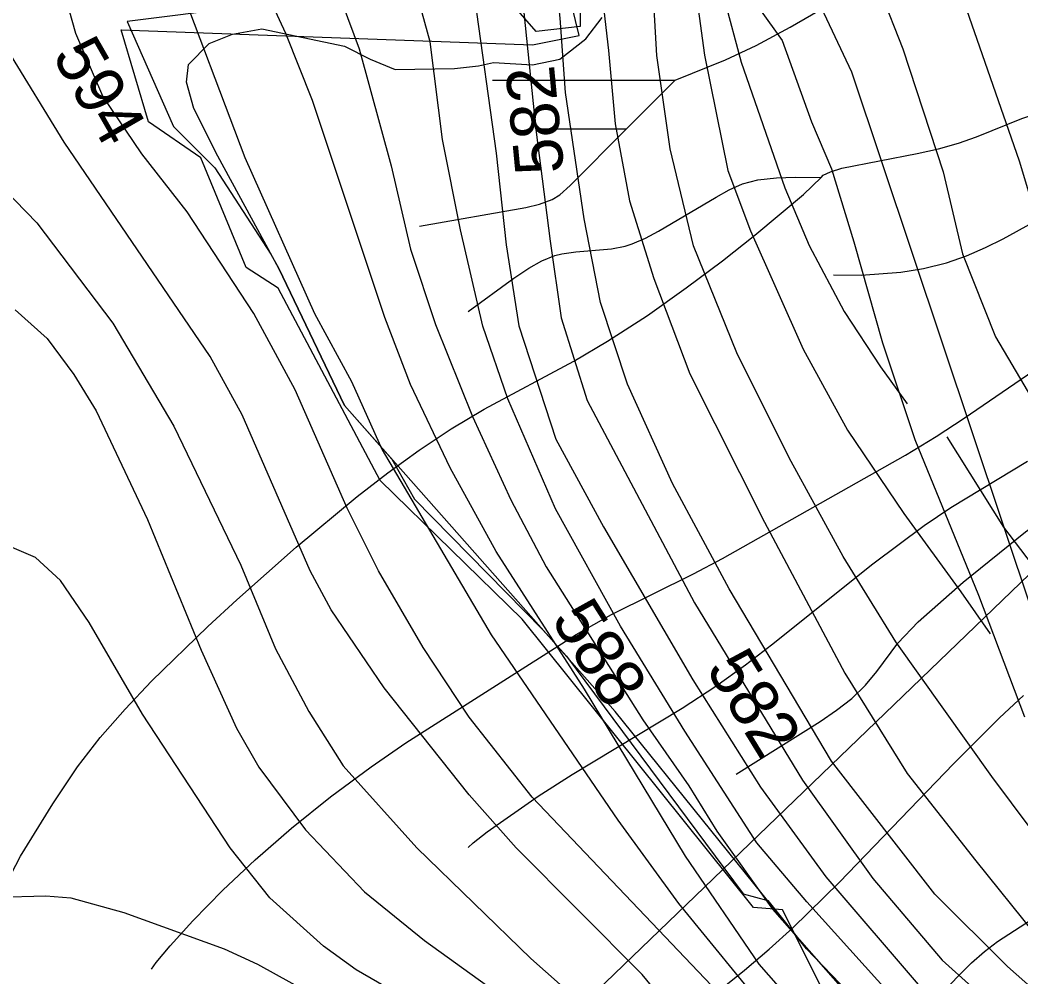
# Model space of a CAD drawing. Extents: x -709584 to -702006, y -1161789 to -1157496.
# Drawn here: x -708051.5 to -707846, y -1159256.1 to -1159059.7 of the extents above; entities that cross this region are included whole.
import ezdxf

# ---------------------------------------------------------------- set-up
doc = ezdxf.new("R2010")
doc.units = 0
for name, color, linetype in [('102_obvod PÚ', 7, 'Continuous'), ('120_vrstevnice hlavní', 7, 'Continuous'), ('121_vrstevnice hlavní_popis', 7, 'Continuous'), ('122_vrstevnice základní', 7, 'Continuous'), ('408_BPEJ_linie', 7, 'Continuous'), ('411_akumulovaný odtok', 7, 'Continuous'), ('419_LPIS PB', 7, 'Continuous')]:
    doc.layers.add(name, color=color, linetype=linetype)

msp = doc.modelspace()

# ---------------------------------------------------------------- linework, layer by layer
at = {"layer": '102_obvod PÚ'}
msp.add_lwpolyline([(-707886.77, -1159258.66), (-707894.98, -1159242.32), (-707900.9, -1159241.82), (-707948.43, -1159182.66), (-707977.59, -1159154.21), (-707998.52, -1159114.69), (-708005.08, -1159110.48), (-708014.36, -1159087.93), (-708025.14, -1159080.58), (-708030.74, -1159061.67), (-707946.25, -1159064.74), (-707936.69, -1159062.88), (-707939.76, -1159050.18), (-707956.24, -1159018.71), (-707933.55, -1159011.72), (-707932.26, -1159006.15), (-707944.32, -1158991.81), (-707921.75, -1158971.03), (-707999.13, -1158885.41)], dxfattribs=at)
at = {"layer": '120_vrstevnice hlavní'}
for points in [[(-707848.73, -1159253.97), (-707863.68, -1159239.08), (-707884.91, -1159211.8), (-707905.93, -1159176.45), (-707917.51, -1159154.82), (-707926.81, -1159134.44), (-707932.34, -1159117.65), (-707935.66, -1159100.46), (-707939.49, -1159074.58), (-707940.61, -1159059.3), (-707941.75, -1159048.16), (-707943.46, -1159040.73), (-707948.46, -1159025.87), (-707951.89, -1159018.44), (-707957.89, -1159007.3), (-707967.47, -1158995.44), (-707982.61, -1158980.3), (-708017.04, -1158950.58), (-708039.04, -1158933.58), (-708068.19, -1158914.44)], [(-707842.05, -1159330.03), (-707850.89, -1159310.21), (-707856.39, -1159300.65), (-707860.67, -1159294.5), (-707886.32, -1159268.74), (-707899.75, -1159253.46), (-707914.89, -1159231.31), (-707935.61, -1159197.02), (-707953.75, -1159168.74), (-707963.18, -1159151.59), (-707971.32, -1159134.45), (-707976.61, -1159120.74), (-707991.47, -1159076.16), (-707996.9, -1159062.45), (-708006.47, -1159041.87), (-708012.9, -1159031.59), (-708021.04, -1159020.59), (-708028.33, -1159012.44), (-708057.61, -1158984.3)], [(-708052.47, -1159119.16), (-708045.9, -1159125.02), (-708040.47, -1159132.45), (-708035.9, -1159139.88), (-708025.33, -1159162.17), (-708014.33, -1159189.02), (-708007.04, -1159205.03), (-708002.47, -1159213.03), (-707992.9, -1159225.88), (-707980.75, -1159238.6), (-707968.47, -1159248.6), (-707938.32, -1159270.31), (-707926.18, -1159280.17), (-707918.61, -1159288.03), (-707901.46, -1159312.46), (-707897.32, -1159320.46), (-707890.01, -1159343.4), (-707888.28, -1159354.49), (-707886.52, -1159378.36), (-707886.98, -1159410.93), (-707888.63, -1159438.56)], [(-707861.24, -1159145.22), (-707849.59, -1159163.75), (-707838.9, -1159177.82), (-707830.11, -1159187.78), (-707818.64, -1159198.87), (-707809.34, -1159206.24), (-707800.21, -1159214.99), (-707794.42, -1159223.01)], [(-707727.11, -1159458.36), (-707732.55, -1159449.76), (-707767.65, -1159390.93), (-707781.94, -1159363.63), (-707798.19, -1159323.19), (-707807.67, -1159303.33), (-707819.32, -1159283.95), (-707834.55, -1159266.55), (-707848.73, -1159253.97)]]:
    msp.add_lwpolyline(points, dxfattribs=at)
at = {"layer": '122_vrstevnice základní'}
for points in [[(-708017.33, -1158915.44), (-707989.9, -1158936.01), (-707943.61, -1158972.58), (-707928.61, -1158987.87), (-707921.2, -1158999.9), (-707917.92, -1159008.14), (-707915.32, -1159017.92), (-707914.27, -1159025.99), (-707914.09, -1159032.86), (-707912.89, -1159052.82), (-707910.97, -1159066.9), (-707906.21, -1159090.56), (-707901.54, -1159102.92), (-707890.72, -1159127.26), (-707881.58, -1159143.89), (-707870.06, -1159160.94), (-707858.35, -1159177.06), (-707852.34, -1159185.63)], [(-708042.18, -1158921.87), (-708027.33, -1158933.01), (-707999.9, -1158955.01), (-707985.18, -1158967.87), (-707963.04, -1158986.01), (-707952.04, -1158996.3), (-707943.89, -1159005.3), (-707939.87, -1159014.34), (-707935.04, -1159028.05), (-707930.67, -1159065.95), (-707929.33, -1159081), (-707926.38, -1159096.77), (-707921.37, -1159112.72), (-707913.95, -1159132.26), (-707898.64, -1159162.73), (-707882.13, -1159193.75), (-707869.39, -1159214.3), (-707855.28, -1159232.28), (-707843.15, -1159247.3)], [(-707833.26, -1159239.13), (-707840.08, -1159230.91), (-707851.96, -1159214.97), (-707871.68, -1159187.3), (-707882.53, -1159169.82), (-707893.61, -1159149.57), (-707904.3, -1159127.97), (-707913.2, -1159106.04), (-707918.05, -1159086.14), (-707920.74, -1159066.95), (-707921.64, -1159051.33), (-707922.01, -1159039.15), (-707922.89, -1159025.24), (-707925.46, -1159014.73), (-707935.61, -1158999.02), (-707949.32, -1158982.58), (-707958.89, -1158973.44), (-707981.32, -1158955.87), (-707999.9, -1158942.16), (-708020.33, -1158924.73)], [(-708055.61, -1158933.15), (-708049.04, -1158938.15), (-708031.61, -1158952.87), (-707996.32, -1158985.58), (-707978.75, -1159003.16), (-707966.75, -1159016.73), (-707961.75, -1159023.59), (-707955.46, -1159034.16), (-707951.46, -1159044.16), (-707948.04, -1159058.16), (-707945.61, -1159082.16), (-707942.67, -1159105.07), (-707940.4, -1159120.83), (-707935.05, -1159137.78), (-707913.05, -1159179.33), (-707890.84, -1159215.71), (-707876.4, -1159235.89), (-707862.19, -1159252.63), (-707850, -1159263.57)], [(-708062.19, -1158941.44), (-708041.61, -1158957.87), (-707986.75, -1159009.02), (-707975.9, -1159020.73), (-707968.18, -1159031.02), (-707964.47, -1159037.02), (-707961.75, -1159043.02), (-707958.18, -1159055.02), (-707953.75, -1159087.02), (-707951.69, -1159105.82), (-707949.08, -1159122.43), (-707941.5, -1159145.71), (-707931.7, -1159163.67), (-707913.37, -1159195.09), (-707899.45, -1159217.16), (-707886.05, -1159235.55), (-707866.31, -1159258.63)], [(-707863.48, -1159270.01), (-707889.93, -1159240.68), (-707900.23, -1159228.54), (-707915, -1159205.64), (-707928.23, -1159184.1), (-707941.53, -1159159.99), (-707951.34, -1159137.42), (-707956.51, -1159122.54), (-707961.04, -1159102.73), (-707964.75, -1159084.16), (-707967.32, -1159064.16), (-707970.04, -1159054.16), (-707975.32, -1159041.3), (-707981.32, -1159031.3), (-707992.04, -1159018.73), (-708022.75, -1158988.73), (-708049.33, -1158965.87), (-708069.76, -1158950.58)], [(-708060.76, -1158967.73), (-708046.33, -1158980.3), (-708030.76, -1158995.87), (-708006.47, -1159018.87), (-708001.9, -1159024.02), (-707995.75, -1159033.02), (-707990.18, -1159043.3), (-707981.9, -1159065.59), (-707975.32, -1159089.59), (-707971.32, -1159106.73), (-707966.18, -1159122.16), (-707958.61, -1159141.02), (-707950.75, -1159158.17), (-707943.46, -1159171.88), (-707923.61, -1159203.31), (-707914.18, -1159216.88), (-707908.46, -1159226.17), (-707897.03, -1159242.17), (-707882.6, -1159258.6), (-707852.45, -1159289.7), (-707844.21, -1159301.66), (-707839.06, -1159311.23), (-707836.31, -1159317.9)], [(-707886.99, -1158990.28), (-707879.04, -1159004.38), (-707869.7, -1159025.35), (-707858.82, -1159052.74), (-707846.38, -1159088.58), (-707840.83, -1159106.99), (-707835.29, -1159122.12), (-707829.93, -1159132.95), (-707818.68, -1159151.56), (-707806.43, -1159164.96), (-707786.09, -1159180.23), (-707759.76, -1159199.37)], [(-707898.3, -1158994.45), (-707889.48, -1159017.13), (-707879.4, -1159042.22), (-707870.23, -1159065.6), (-707861.97, -1159090.81), (-707857.98, -1159107.66), (-707851.23, -1159124.68), (-707836.26, -1159150.07), (-707826.25, -1159163.98), (-707794.33, -1159201.65), (-707771.35, -1159226.36), (-707755.65, -1159245.77), (-707746.68, -1159257.27), (-707740.67, -1159256.4), (-707729.8, -1159271.34), (-707715.51, -1159298.9), (-707703.93, -1159322.1), (-707687.5, -1159342.8), (-707674.05, -1159354.64), (-707659.74, -1159365.89), (-707631.31, -1159397.03), (-707621.2, -1159409.47), (-707587.64, -1159457.53), (-707575.99, -1159476.79)], [(-708054.47, -1158997.73), (-708049.33, -1159003.73), (-708033.47, -1159025.02), (-708025.75, -1159037.87), (-708019.76, -1159049.61), (-708005.33, -1159087.88), (-707991.04, -1159119.88), (-707983.47, -1159133.88), (-707977.18, -1159147.88), (-707954.75, -1159185.88), (-707928.75, -1159223.88), (-707916.32, -1159241.03), (-707897.6, -1159263.89), (-707880.32, -1159283.6), (-707872.18, -1159293.89), (-707864.54, -1159306.3), (-707859.39, -1159315.69), (-707853.89, -1159329.52), (-707849.83, -1159344.16)], [(-707912.52, -1159000.46), (-707910.44, -1159007.16), (-707909.04, -1159019.36), (-707909.02, -1159029.15), (-707909.34, -1159036.88), (-707908.49, -1159046.82), (-707906.92, -1159055.24), (-707903.46, -1159068.29), (-707894.51, -1159094.12), (-707889.51, -1159105.96), (-707882.26, -1159119.52), (-707874.84, -1159130.84), (-707869.33, -1159138.48)], [(-707867.58, -1159317.94), (-707874.1, -1159305.66), (-707884.32, -1159288.17), (-707890.6, -1159279.6), (-707908.18, -1159259.31), (-707946.32, -1159219.17), (-707959.32, -1159202.74), (-707968.75, -1159188.45), (-707977.9, -1159172.74), (-707984.32, -1159159.88), (-707995.04, -1159135.59), (-708003.47, -1159119.88), (-708017.18, -1159099.02), (-708026.47, -1159087.16), (-708034.47, -1159075.3), (-708040.04, -1159062.45), (-708042.04, -1159055.3), (-708045.18, -1159038.16), (-708048.47, -1159028.16), (-708053.18, -1159019.59)], [(-707860.77, -1159442.01), (-707862.06, -1159427.77), (-707863.48, -1159401.14), (-707865.61, -1159375.43), (-707869.07, -1159351.37), (-707873.18, -1159336.46), (-707883.32, -1159311.6), (-707889.6, -1159299.6), (-707897.18, -1159287.89), (-707923.75, -1159255.6), (-707949.61, -1159229.6), (-707959.32, -1159218.74), (-707976.75, -1159196.74), (-707987.61, -1159180.74), (-707991.9, -1159172.74), (-708005.9, -1159140.74), (-708012.47, -1159128.74), (-708042.47, -1159084.73), (-708054.04, -1159065.88)], [(-708057.04, -1159092.16), (-708048.04, -1159101.31), (-708032.47, -1159121.88), (-708019.9, -1159143.02), (-708006.18, -1159171.59), (-707999.04, -1159188.74), (-707992.18, -1159201.6), (-707985.18, -1159212.74), (-707970.04, -1159229.6), (-707946.61, -1159252.31), (-707930.32, -1159266.74), (-707919.46, -1159277.31), (-707907.18, -1159291.03), (-707896.32, -1159305.89), (-707886.32, -1159324.46), (-707880.89, -1159338.46), (-707876.5, -1159361.48), (-707874.74, -1159387.24), (-707874.05, -1159419.86), (-707873.91, -1159440.39)], [(-707900.29, -1159437.18), (-707899.15, -1159413.19), (-707897.42, -1159381.75), (-707898.3, -1159366.41), (-707901.32, -1159347.6), (-707912.18, -1159318.46), (-707915.89, -1159309.89), (-707921.61, -1159299.6), (-707929.04, -1159289.31), (-707939.75, -1159279.03), (-707951.04, -1159271.89), (-707966.75, -1159263.74), (-707982.47, -1159254.6), (-707989.18, -1159249.74), (-708000.18, -1159239.88), (-708008.33, -1159229.6), (-708026.33, -1159202.17), (-708037.33, -1159183.31), (-708043.18, -1159174.74), (-708048.33, -1159170.02), (-708053.61, -1159167.74)], [(-708056.19, -1159239.74), (-708046.18, -1159239.46), (-708041.04, -1159239.88), (-708030.18, -1159242.88), (-708009.61, -1159250.31), (-708002.75, -1159253.46), (-707992.47, -1159259.17), (-707977.04, -1159269.6), (-707959.89, -1159279.17), (-707954.75, -1159282.74), (-707946.04, -1159290.89), (-707938.04, -1159300.17), (-707924.04, -1159320.75), (-707917.83, -1159338.72), (-707913.71, -1159353.53), (-707911.62, -1159374.65), (-707910.68, -1159413.59), (-707911.48, -1159435.56)]]:
    msp.add_lwpolyline(points, dxfattribs=at)
at = {"layer": '408_BPEJ_linie'}
for points in [[(-707936.5, -1159057.5), (-707936.5, -1159061), (-707945.5, -1159062), (-707952, -1159054.5)], [(-708006, -1159057), (-708029.5, -1159060), (-708020, -1159081.5), (-708011.5, -1159090), (-707999.99, -1159107.7), (-707998.37, -1159110.7), (-707984.85, -1159138.82), (-707975.15, -1159149.78), (-707970.5, -1159158), (-707944.2, -1159184.75), (-707939.3, -1159190.27), (-707903, -1159239), (-707897.98, -1159240.41), (-707890, -1159250.3), (-707883.64, -1159256.93)]]:
    msp.add_lwpolyline(points, dxfattribs=at)
at = {"layer": '411_akumulovaný odtok'}
for p, q in [((-707954.49, -1159072), (-707916.99, -1159072)), ((-707926.99, -1159082), (-707916.99, -1159072)), ((-707944.49, -1159082), (-707926.99, -1159082))]:
    msp.add_line(p, q, dxfattribs=at)
for points in [[(-707916.99, -1159072), (-707906.66, -1159067.84), (-707900.39, -1159064.89), (-707893.38, -1159061.16), (-707885.95, -1159056.84), (-707878.44, -1159052.19), (-707864.41, -1159042.9), (-707847.45, -1159030.99), (-707827.76, -1159017.68), (-707823.58, -1159014.67), (-707818.4, -1159010.5), (-707813.39, -1159006.07), (-707808.51, -1159001.46), (-707799, -1158991.88), (-707775.52, -1158967.4), (-707765.82, -1158957.95), (-707760.78, -1158953.44), (-707750.33, -1158945), (-707728.65, -1158929.01)], [(-707886.99, -1159092), (-707886.58, -1159091.5), (-707885.13, -1159090.82), (-707882.74, -1159090.09), (-707867.29, -1159087.06), (-707862.94, -1159086.1), (-707858.8, -1159084.97), (-707855.09, -1159083.66), (-707845.81, -1159079.87), (-707842.84, -1159078.96), (-707830.71, -1159075.83), (-707827.77, -1159074.76), (-707824.73, -1159073.33), (-707818.91, -1159069.8), (-707813.3, -1159065.71), (-707807.82, -1159061.3), (-707799.83, -1159054.31), (-707794.49, -1159049.2), (-707781.23, -1159035.23), (-707736.99, -1158987)], [(-707969.49, -1159102), (-707947.64, -1159098.12), (-707944.85, -1159097.48), (-707942.24, -1159096.51), (-707940.69, -1159095.52), (-707938.54, -1159093.67), (-707926.99, -1159082)], [(-708054.18, -1159236.7), (-708051.38, -1159231.32), (-708044.8, -1159220.59), (-708039.73, -1159212.98), (-708035.05, -1159206.97), (-708029.93, -1159201.11), (-708024.49, -1159195.37), (-708012.97, -1159184.15), (-708007, -1159178.65), (-707994.81, -1159167.85), (-707982.28, -1159157.48), (-707975.96, -1159152.62), (-707969.52, -1159147.98), (-707962.95, -1159143.6), (-707956.23, -1159139.55), (-707937.81, -1159129.66), (-707930.86, -1159125.6), (-707922.65, -1159120.29), (-707914.71, -1159114.67), (-707907.28, -1159109.08), (-707900.62, -1159103.81), (-707890.67, -1159095.46), (-707886.99, -1159092)], [(-707959.49, -1159119.5), (-707950.1, -1159112.63), (-707947.02, -1159110.58), (-707944.39, -1159109.11), (-707941.67, -1159108.03), (-707940.28, -1159107.69), (-707937.4, -1159107.28), (-707930.09, -1159106.65), (-707927.24, -1159106.09), (-707925.84, -1159105.64), (-707923.09, -1159104.45), (-707920.41, -1159103.04), (-707908.55, -1159096.01), (-707905.89, -1159094.55), (-707903.16, -1159093.3), (-707900.01, -1159092.44), (-707896.2, -1159092.03), (-707892.36, -1159091.91), (-707886.99, -1159092)], [(-707884.49, -1159112), (-707878.78, -1159112.07), (-707870.66, -1159111.41), (-707866.01, -1159110.65), (-707861.29, -1159109.49), (-707857.16, -1159108.07), (-707853.26, -1159106.38), (-707849.68, -1159104.59), (-707843.57, -1159101.2)], [(-708024.49, -1159254.5), (-708023.56, -1159253.14), (-708020.66, -1159249.67), (-708016.01, -1159244.56), (-708009.86, -1159238.29), (-708003.21, -1159232.06), (-707995.75, -1159225.58), (-707987.74, -1159219.12), (-707979.43, -1159212.95), (-707972.27, -1159208.06), (-707937.29, -1159185.81), (-707930.05, -1159181.69), (-707913.21, -1159173.34), (-707907.3, -1159170.17), (-707869.73, -1159148.98), (-707863.42, -1159145.13), (-707857.68, -1159141.39), (-707832.97, -1159124.49)], [(-707879.49, -1159279.5), (-707871.24, -1159269.62), (-707865.23, -1159262.7), (-707859.03, -1159256.04), (-707856.14, -1159253.22), (-707853.48, -1159250.89), (-707850.78, -1159248.8), (-707840.52, -1159242.21), (-707838.02, -1159240.46), (-707835.24, -1159238.24), (-707832.57, -1159235.85), (-707827.46, -1159230.74), (-707820.08, -1159222.64), (-707788.78, -1159186.5), (-707776.94, -1159172.44), (-707771.72, -1159165.47), (-707769.02, -1159161.52), (-707763.9, -1159153.53), (-707756.99, -1159142)], [(-707959.49, -1159229.5), (-707958.5, -1159228.56), (-707955.57, -1159226.31), (-707945.1, -1159218.98), (-707938.17, -1159214.52), (-707915.56, -1159200.93), (-707908.67, -1159196.38), (-707902.56, -1159192), (-707897.24, -1159187.92), (-707876.44, -1159171.32), (-707865.84, -1159163.43), (-707860.39, -1159159.76), (-707844.68, -1159150.23)], [(-707989.49, -1159324.5), (-707987.25, -1159322.35), (-707981.86, -1159316.53), (-707974.87, -1159308.28), (-707971.27, -1159303.63), (-707960.42, -1159288.01), (-707957.58, -1159284.34), (-707954.57, -1159280.79), (-707948.18, -1159273.92), (-707931.35, -1159257.31), (-707821.99, -1159152)], [(-707904.49, -1159214.5), (-707887.23, -1159203.66), (-707883.9, -1159201.36), (-707880.75, -1159198.92), (-707877.88, -1159196.21), (-707875.61, -1159193.41), (-707871.27, -1159187.57), (-707867.09, -1159183.19), (-707857.85, -1159175.09), (-707845.09, -1159164.73), (-707841.76, -1159162.37), (-707838.04, -1159160.11), (-707831.02, -1159156.43), (-707821.99, -1159152)], [(-707915.12, -1159264.65), (-707902.77, -1159254.71), (-707897.71, -1159250.38), (-707892.86, -1159246.02), (-707883.23, -1159236.62), (-707859.88, -1159212.35), (-707850.37, -1159202.9), (-707845.48, -1159198.35)]]:
    msp.add_lwpolyline(points, dxfattribs=at)
at = {"layer": '419_LPIS PB'}
for points in [[(-707843.5, -1159181.6), (-707880.71, -1159070.37), (-707894.38, -1159041.28), (-707907.77, -1159009.43), (-707907.27, -1159005.91), (-707904.77, -1159003.4), (-707885.25, -1158993.86), (-707863.72, -1158983.82), (-707856.21, -1158982.31), (-707849.71, -1158983.82), (-707841.2, -1158990.85)], [(-707899.7, -1159057.4), (-707895, -1159063.9), (-707889, -1159080.6), (-707884.9, -1159090.2), (-707880.3, -1159105.2), (-707874.4, -1159125.9), (-707867.8, -1159145.8), (-707854.7, -1159177.7), (-707845.3, -1159202.7)], [(-707876.3, -1159264.6), (-707890, -1159250.3), (-707929.29, -1159201.58), (-707984.85, -1159138.82), (-707998.37, -1159110.7), (-708010.88, -1159087.6), (-708015.8, -1159077.8), (-708017.3, -1159072.4), (-708016.9, -1159068.8), (-708012.7, -1159064.5), (-708007.9, -1159062.6), (-708001.87, -1159061.49), (-707984.85, -1159065.01), (-707979.6, -1159067.7), (-707974.5, -1159069.8), (-707962.3, -1159069.6), (-707957.4, -1159069.1), (-707954.3, -1159068.4), (-707946.3, -1159068.9), (-707940.7, -1159067.7), (-707935.3, -1159063.5), (-707931.95, -1159059.13)]]:
    msp.add_lwpolyline(points, dxfattribs=at)

# ---------------------------------------------------------------- texts
at = {"layer": '121_vrstevnice hlavní_popis'}
for s, rotation, p in [('594', 299.8543, (-708045.03, -1159066.95)), ('582', 95.4778, (-707939.77, -1159090.9)), ('588', 302.3761, (-707942.64, -1159182.73)), ('582', 301.5133, (-707910.84, -1159192.84))]:
    msp.add_text(s, height=10, rotation=rotation, dxfattribs=at).set_placement(p)

doc.saveas('drawing.dxf')
